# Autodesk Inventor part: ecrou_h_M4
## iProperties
Created: 2011-01
Part Number: ecrou_h_M4
Document SubType Name: Modeling
Designer: eric
Density: 1 g/cm^3
Mass: 0.193373 g
Surface Area: 3.52549 cm^2
Volume: 0.193373 cm^3
Author: eric
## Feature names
1. Base1
